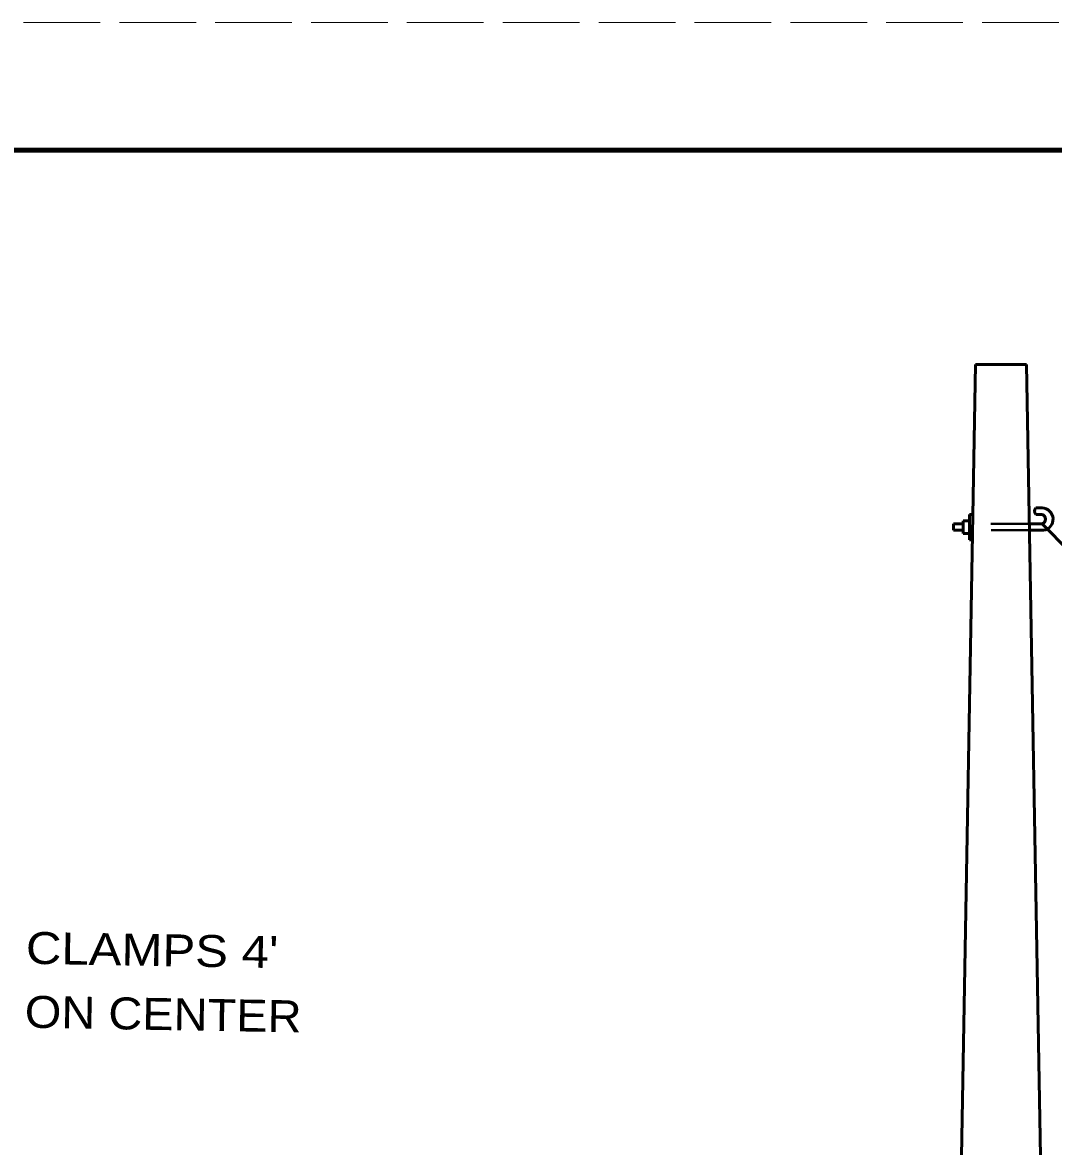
# Model space of a CAD drawing. Extents: x 12366 to 13046, y 9129 to 9570.
# Drawn here: x 12665.9 to 12746.6, y 9481.6 to 9569.5 of the extents above; entities that cross this region are included whole.
import ezdxf

# ---------------------------------------------------------------- set-up
doc = ezdxf.new("R2010")
doc.units = 0
doc.linetypes.add('LONG_DASHED', pattern=[7.5, 6, -1.5])
doc.linetypes.add('MEDIUM_DASHED', pattern=[4.5, 3, -1.5])
doc.layers.add('1', color=7, linetype='Continuous', lineweight=53)
doc.layers.add('61', color=7, linetype='Continuous', lineweight=35)

msp = doc.modelspace()

# ---------------------------------------------------------------- linework, layer by layer
at = {"layer": '1'}
for p, q in [((12740.471, 9542.779), (12737.941, 9397.801)), ((12744.471, 9542.779), (12740.471, 9542.779)), ((12744.471, 9542.779), (12745.776, 9468.032)), ((12745.689, 9531.553), (12745.189, 9531.553)), ((12740.004, 9531.053), (12740.004, 9529.053)), ((12740.004, 9531.053), (12740.267, 9531.053)), ((12745.689, 9531.053), (12745.189, 9531.053)), ((12739.504, 9530.303), (12738.754, 9530.303)), ((12738.754, 9530.303), (12738.754, 9529.803)), ((12739.504, 9529.803), (12738.754, 9529.803)), ((12739.504, 9530.553), (12739.504, 9529.553)), ((12739.504, 9530.553), (12739.991, 9530.553)), ((12744.689, 9530.303), (12745.689, 9530.303)), ((12744.698, 9529.803), (12745.798, 9529.803)), ((12745.687, 9530.302), (12747.808, 9528.181)), ((12739.504, 9529.553), (12740, 9529.553)), ((12740.004, 9529.053), (12740.232, 9529.053))]:
    msp.add_line(p, q, dxfattribs=at)
at = {"layer": '1', "linetype": 'MEDIUM_DASHED', "lineweight": 40}
for p, q in [((12744.698, 9529.803), (12740.245, 9529.803)), ((12744.689, 9530.303), (12740.254, 9530.303))]:
    msp.add_line(p, q, dxfattribs=at)
at = {"layer": '1'}
for centre, radius, start, end in [((12745.473, 9531.303), 0.378, 138.58649, 221.41351), ((12745.667, 9530.673), 0.88, 278.54206, 88.56984), ((12745.56, 9530.678), 0.397, 289.03349, 70.96651)]:
    msp.add_arc(centre, radius, start, end, dxfattribs=at)
at = {"layer": '61', "linetype": 'LONG_DASHED', "lineweight": 13}
msp.add_line((12365.992, 9569.533), (13046.012, 9569.533), dxfattribs=at)
at = {"layer": '61', "lineweight": 158}
msp.add_lwpolyline([(13035.032, 9559.533), (12395.992, 9559.533), (12395.992, 9139.513)], dxfattribs=at)

# ---------------------------------------------------------------- texts
at = {"layer": '1'}
for s, width, p in [("CLAMPS 4'", 1.15, (12666.158, 9495.895)), ('ON CENTER', 1.1, (12666.07, 9490.896))]:
    msp.add_text(s, height=2.5, rotation=359, dxfattribs=dict(at, width=width)).set_placement(p)

doc.saveas('drawing.dxf')
